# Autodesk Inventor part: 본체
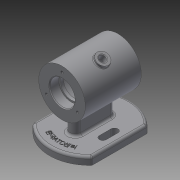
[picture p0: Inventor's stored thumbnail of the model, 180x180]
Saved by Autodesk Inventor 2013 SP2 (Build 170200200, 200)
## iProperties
Created: 2022-02
Part Number: 본체
Material: Generic
Document SubType Name: Modeling
Designer: i
Density: 1 g/cm^3
Author: i
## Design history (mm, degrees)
sketch "스케치1"
  geometry: L1 (-36, 0)-(36, 0); L2 (-36, 0)-(-36, 30); L3 (-36, 30)-(36, 30); L4 (36, 30)-(36, 0); L5 (-36, 16)-(-24, 16); L6 (-24, 16)-(-24, 14); L7 (-24, 14)-(-20, 14); L8 (-20, 14)-(-20, 25); L9 (-20, 25)-(20, 25); L10 (20, 25)-(20, 14); L11 (20, 14)-(24, 14); L12 (24, 14)-(24, 16); L13 (24, 16)-(36, 16); 2 further points
  constraints: 26 end point, 7 perpendicular, 5 parallel, 2 point on line, 1 coincident, 1 horizontal, 1 midpoint
  dimensions: "d0" = 72 distance of L1.start L1.end; "d1" = 60 diameter of L3 L1; "d2" = 32 diameter of L5 L1; "d3" = 32 diameter of L13 L1; "d4" = 28 diameter of L7 L1; "d5" = 28 diameter of L11 L1; "d6" = 12 distance of L5.start L5.end; "d7" = 12 distance of L13.end L12.end; "d9" = 50 diameter of L9 L1; "d10" = 40 distance between parallel lines of L10 L8; "d11" = 4 distance between parallel lines of L6 L8
revolve "회전1" sketch "스케치1" stored, may be unused: angle "d12" = 90 deg
fillet "모깎기1" dims "d13" = 3
fillet "모깎기2" dims "d14" = 0.3
sketch "스케치2" dims "d15" = 46
  geometry: C1 r 16 at (0, 0) reference; 2 further points
  constraints: 2 vertical alignment, 1 coincident, 2 other
hole "구멍1" sketch "스케치2" at (0, 23) diameter "d16" = 3.242; stored, may be unused: countersink angle "d20" = 90 deg, drill point angle "d22" = 118 deg; dims "d17" = 8, "d18" = 4, "d19" = 2, "d21" = 10
sketch "스케치3"
  geometry: L1 (0, 0)-(28.579, 16.5); L2 (0, 0)-(33, 0); 1 further point
  constraints: 4 end point, 1 coincident, 1 equal length, 1 horizontal
  dimensions: "d28" = 33 distance of L1.start L1.end; "d29" = 30 deg angle of L2 L1
node "작업 평면1"
sketch "스케치4"
  geometry: C1 r 8 at (0, 0); 1 further point
  constraints: 1 centre point, 1 coincident
  dimensions: "d30" = 16 diameter of C1
extrude "돌출1" join sketch "스케치4" stored distance "d31" = 0; taper "d32" = 0 deg
sketch "스케치5"
  geometry: C1 r 8 at (0, 0) reference; C2 r 4 at (0, 0)
  constraints: 1 centre point, 1 coincident
  dimensions: "d33" = 8 diameter of C2
extrude "돌출2" cut sketch "스케치5" stored distance "d34" = 10; taper "d35" = 0 deg
fillet "모깎기3" dims "d36" = 1
fillet "모깎기4" dims "d37" = 1
node "작업 평면2"
sketch "스케치6"
  geometry: C1 r 52 at (0, 0); 1 further point
  constraints: 1 centre point, 1 coincident
  dimensions: "d39" = 104 diameter of C1
extrude "돌출3" join sketch "스케치6" distance "d40" = 10; taper "d41" = 0 deg
sketch "스케치7"
  geometry: L1 (-52, 38)-(52, 38); L2 (52, 38)-(52, -38); L3 (52, -38)-(-52, -38); L4 (-52, -38)-(-52, 38); L5 (-52, 38)-(52, -38); L6 (52, 38)-(-52, -38); L7 (-52, -38)-(52, -38); L8 (52, -38)-(52, -52); L9 (52, -52)-(-52, -52); L10 (-52, -52)-(-52, -38); A1 r 52 centre (0, 0) between (-52, 0) and (0, -52) reference; 1 further point
  constraints: 20 end point, 5 midpoint, 4 parallel, 2 horizontal, 2 perpendicular, 2 point on circle, 1 vertical alignment
  dimensions: "d42" = 76 distance of L1.end L2.end
extrude "돌출4" cut sketch "스케치7" stored distance "d43" = 10; taper "d44" = 0 deg
sketch "스케치8"
  geometry: L1 (-19, 7)-(19, 7); L2 (19, 7)-(19, -7); L3 (19, -7)-(-19, -7); L4 (-19, -7)-(-19, 7); L5 (-19, 7)-(19, -7); L6 (19, 7)-(-19, -7); A1 r 52 centre (0, 0) between (35.496, -38) and (35.496, 38) reference; A2 r 7 centre (-19, 0) between (-19, 7) and (-19, -7); A3 r 7 centre (19, 0) between (19, -7) and (19, 7)
  constraints: 12 end point, 4 midpoint, 4 point on circle, 2 centre point, 2 parallel, 1 horizontal, 1 perpendicular
  dimensions: "d45" = 38 distance of L2.end L3.end; "d46" = 14 distance of L1.end L2.end
extrude "돌출5" join sketch "스케치8" stored distance "d47" = 10; taper "d48" = 0 deg
sketch "스케치9"
  geometry: L1 (-7.5, 28.5)-(7.5, 28.5); L2 (7.5, 28.5)-(7.5, 19.5); L3 (7.5, 19.5)-(-7.5, 19.5); L4 (-7.5, 19.5)-(-7.5, 28.5); L5 (-7.5, 28.5)-(7.5, 19.5); L6 (7.5, 28.5)-(-7.5, 19.5); A1 r 52 centre (0, 0) between (-35.496, 38) and (-35.496, -38) reference; A2 r 4.5 centre (-7.5, 24) between (-7.5, 28.5) and (-7.5, 19.5); A3 r 4.5 centre (7.5, 24) between (7.5, 19.5) and (7.5, 28.5); 2 further points
  constraints: 12 end point, 5 midpoint, 4 point on circle, 2 centre point, 2 parallel, 1 horizontal, 1 perpendicular, 1 vertical alignment
  dimensions: "d49" = 15 distance of L2.end L3.end; "d50" = 9 distance of L1.end L2.end; "d51" = 24 distance of point (0, 24) A1.centre
extrude "돌출6" cut sketch "스케치9" stored distance "d52" = 10; taper "d53" = 0 deg
sketch "스케치10"
  geometry: C1 r 42.5 at (0, 0); A1 r 52 centre (0, 0) between (35.496, -38) and (35.496, 38) reference
  constraints: 1 centre point, 1 coincident, 1 other
  dimensions: "d54" = 85 diameter of C1
feature "엠보싱1" sketch "스케치10" dims "d0" = 72, "d1" = 60, "d2" = 32, "d3" = 32, "d4" = 28, "d5" = 28, "d6" = 12, "d7" = 12, "d9" = 50, "d10" = 40, "d11" = 4, "d14" = 0.3, "d56" = 0.5, "d57" = 0
chamfer "모따기1" distance "d58" = 1; stored, may be unused: second distance "d59" = 2, angle "d60" = 45 deg
fillet "모깎기5" dims "d61" = 3
fillet "모깎기6" dims "d62" = 3
fillet "모깎기7" dims "d63" = 3
node "솔리드1"
pattern_circular "원형 패턴1" dims angle "d24" = 360 deg
mirror "대칭1"
mirror "대칭2"
mirror "대칭3"
other parameters: "d38" = -62
